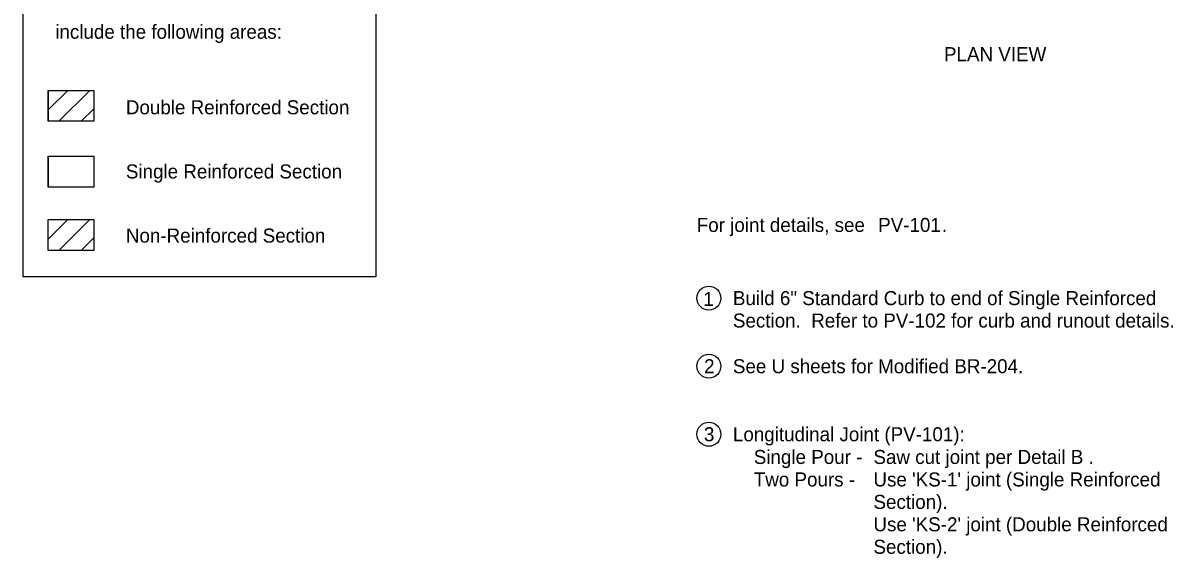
# Model space of a CAD drawing. Extents: x 5546 to 81668, y 3174 to 15999.
# Drawn here: x 21663 to 23174, y 11622 to 12326 of the extents above; entities that cross this region are included whole.
import ezdxf

# ---------------------------------------------------------------- set-up
doc = ezdxf.new("R2010")
doc.units = 0
for name, color, linetype in [('PS_BOLT', 7, 'Continuous'), ('PS_DIM', 7, 'Continuous'), ('tdCoShieldStRte', 7, 'Continuous')]:
    doc.layers.add(name, color=color, linetype=linetype)

msp = doc.modelspace()

# ---------------------------------------------------------------- linework, layer by layer
at = {"layer": 'PS_DIM'}
for p, q in [((21696, 12237.2), (21756, 12237.2)), ((21696, 12237.2), (21696, 12196.5)), ((21696, 12211.4), (21721.8, 12237.2)), ((21710.3, 12196.5), (21751, 12237.2)), ((21756, 12237.2), (21756, 12196.5)), ((21739.5, 12196.5), (21756, 12213)), ((21756, 12196.5), (21696, 12196.5)), ((21696, 12150.7), (21756, 12150.7)), ((21696, 12150.7), (21696, 12110)), ((21756, 12150.7), (21756, 12110)), ((21756, 12110), (21696, 12110)), ((21696, 12041.5), (21721.8, 12067.3)), ((21710.3, 12026.6), (21751, 12067.3)), ((21739.5, 12026.6), (21756, 12043.1))]:
    msp.add_line(p, q, dxfattribs=at)
for points in [[(21663.1, 12373.8), (22126.6, 12373.8), (22126.6, 11991.7), (21663.1, 11991.7)], [(21696, 12067.3), (21756, 12067.3), (21756, 12026.6), (21696, 12026.6)]]:
    msp.add_lwpolyline(points, close=True, dxfattribs=at)
for centre in [(22564.5, 11963.8), (22564.5, 11874.3), (22564.5, 11784.7)]:
    msp.add_circle(centre, 15.8, dxfattribs=at)
at = {"layer": 'tdCoShieldStRte'}
for p, q in [((21696, 12237.2), (21756, 12237.2)), ((21696, 12196.5), (21696, 12237.2)), ((21756, 12237.2), (21756, 12196.5)), ((21756, 12196.5), (21696, 12196.5)), ((21696, 12150.7), (21756, 12150.7)), ((21696, 12110), (21696, 12150.7)), ((21756, 12150.7), (21756, 12110)), ((21756, 12110), (21696, 12110))]:
    msp.add_line(p, q, dxfattribs=at)

# ---------------------------------------------------------------- texts
at = {"layer": 'PS_BOLT'}
for s, height, p in [('include the following areas:', 18.466, (21705.5, 12305.1)), ('PLAN VIEW', 18.47, (22873.5, 12275.6)), ('Double Reinforced Section', 18.466, (21798.3, 12205.7)), ('Single Reinforced Section', 18.466, (21798.3, 12121.3)), ('For joint details, see ', 18.466, (22548.6, 12050.9)), ('PV-101', 18.47, (22787, 12050.9)), ('Non-Reinforced Section', 18.466, (21798.3, 12036.9)), ('.', 18.5, (22870.7, 12050.9)), ('1', 18.5, (22557.2, 11953.6)), ('Build 6" Standard Curb to end of Single Reinforced ', 18.466, (22596.1, 11954.6)), ('Section.  Refer to PV-102 for curb and runout details.', 18.466, (22596.1, 11925.1)), ('2', 18.5, (22558.2, 11865)), ('See U sheets for Modified BR-204.', 18.466, (22596.1, 11865)), ('3', 18.5, (22558, 11775.5)), ('Longitudinal Joint (PV-101):', 18.466, (22596.1, 11775.5)), ('    Single Pour -', 18.466, (22596.1, 11745.6)), ('Saw cut joint per Detail B .', 18.466, (22780.8, 11745.6)), ('    Two Pours -  ', 18.466, (22596.1, 11716)), ("Use 'KS-1' joint (Single Reinforced ", 18.466, (22780.8, 11716)), ('Section).', 18.47, (22780.8, 11686.5)), ("Use 'KS-2' joint (Double Reinforced ", 18.466, (22780.8, 11657)), ('Section).', 18.47, (22780.8, 11627.4))]:
    msp.add_text(s, height=height, dxfattribs=at).set_placement(p)

doc.saveas('drawing.dxf')
